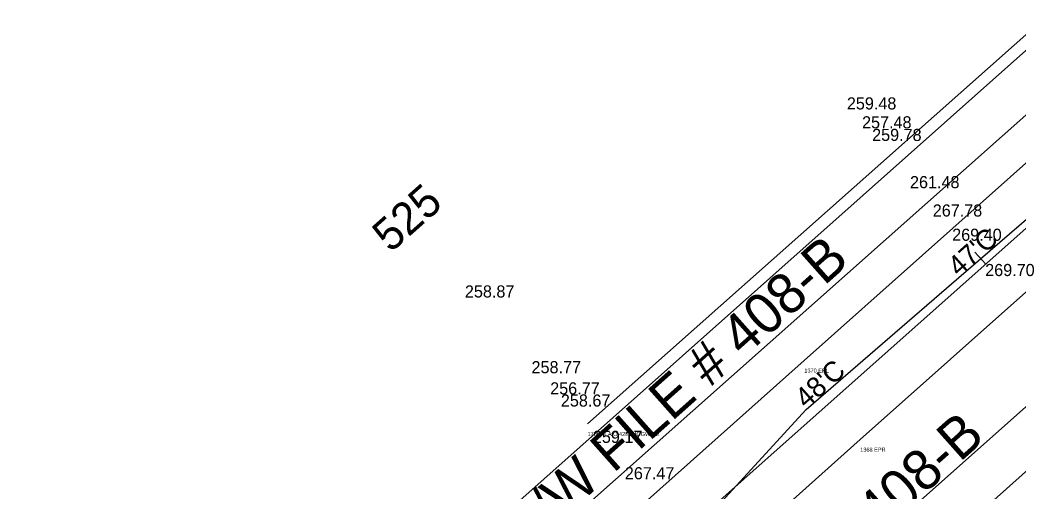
# Model space of a CAD drawing. Extents: x 49683 to 58852, y 49525 to 54803.
# Drawn here: x 53875.1 to 54122.5, y 52022.4 to 52139.1 of the extents above; entities that cross this region are included whole.
import ezdxf

# ---------------------------------------------------------------- set-up
doc = ezdxf.new("R2010")
doc.units = 0
for name, color, linetype in [('Level 1', 7, 'Continuous'), ('Level 11', 7, 'Continuous'), ('Level 13', 7, 'Continuous'), ('Level 18', 7, 'Continuous'), ('Level 19', 7, 'Continuous'), ('Level 20', 7, 'Continuous'), ('Level 21', 7, 'Continuous'), ('Level 25', 7, 'Continuous'), ('Level 3', 7, 'Continuous'), ('Level 32', 7, 'Continuous'), ('Level 48', 7, 'Continuous'), ('Level 53', 7, 'Continuous'), ('Level 58', 7, 'Continuous'), ('Level 8', 7, 'Continuous')]:
    doc.layers.add(name, color=color, linetype=linetype)

msp = doc.modelspace()

# ---------------------------------------------------------------- linework, layer by layer
at = {"layer": 'Level 1'}
for p, q in [((52544.81, 50683.3), (55534.58, 53340.86)), ((54114.5, 52078.58), (54111.84, 52081.57))]:
    msp.add_line(p, q, dxfattribs=at)
at = {"layer": 'Level 11'}
msp.add_line((53894.91, 51911.93), (54324.2, 52292.62), dxfattribs=at)
at = {"layer": 'Level 13'}
for p, q in [((55279.53, 53070), (53969.03, 51905.11)), ((54949.37, 52864.83), (53925.18, 51954.44))]:
    msp.add_line(p, q, dxfattribs=at)
at = {"layer": 'Level 18'}
for p, q in [((54107.86, 52075.28), (54145.7, 52107.97)), ((54070, 52042.61), (54107.86, 52075.28)), ((54036.02, 52005.58), (54070, 52042.61))]:
    msp.add_line(p, q, dxfattribs=at)
at = {"layer": 'Level 19'}
msp.add_line((52714.15, 50773.62), (54181.77, 52078.16), dxfattribs=at)
at = {"layer": 'Level 20'}
msp.add_line((53930.77, 51871.11), (54173.8, 52087.13), dxfattribs=at)
at = {"layer": 'Level 3'}
for p, q in [((54069.54, 52054.72), (54330.23, 52286.79)), ((54083.39, 52035.12), (54346.38, 52269.23)), ((53883.27, 51889.18), (54069.54, 52054.72)), ((53898.74, 51870.57), (54083.39, 52035.12))]:
    msp.add_line(p, q, dxfattribs=at)
at = {"layer": 'Level 8'}
msp.add_line((54015.78, 52039), (54838.64, 52769.14), dxfattribs=at)

# ---------------------------------------------------------------- texts
at = {"layer": 'Level 21'}
msp.add_text('525', height=8, rotation=41.6333, dxfattribs=at).set_placement((53966.97, 52081.24))
at = {"layer": 'Level 25'}
for p in [(53984.2, 51992.86), (54017.83, 51949.17)]:
    msp.add_text("33' R/W FILE # 408-B", height=10, rotation=41.6333, dxfattribs=at).set_placement(p)
at = {"layer": 'Level 32'}
for s, p in [('259.48', (54080.09, 52116.9)), ('257.48', (54083.85, 52112.22)), ('259.78', (54086.35, 52109.1)), ('261.48', (54095.74, 52097.4)), ('267.78', (54101.38, 52090.38)), ('269.40', (54106.2, 52084.37)), ('269.70', (54114.38, 52075.63)), ('258.87', (53985.4, 52070.32)), ('258.77', (54001.92, 52051.56)), ('256.77', (54006.54, 52046.31)), ('258.67', (54009.19, 52043.3)), ('259.17', (54017.12, 52034.3)), ('267.47', (54025.05, 52025.29))]:
    msp.add_text(s, height=3, dxfattribs=at).set_placement(p)
at = {"layer": 'Level 48'}
for s, p in [("47'C", (54107.86, 52075.28)), ("48'C", (54070, 52042.61))]:
    msp.add_text(s, height=5, rotation=41.6334, dxfattribs=at).set_placement(p)
at = {"layer": 'Level 53'}
for s, p in [('1370 EPL', (54069.54, 52051.72)), ('1368 EPR', (54083.39, 52032.12))]:
    msp.add_text(s, height=1, dxfattribs=at).set_placement(p)
at = {"layer": 'Level 58'}
msp.add_text('1705 FLA O 42IN HOGWIRE', height=1, dxfattribs=at).set_placement((54015.78, 52036))

doc.saveas('drawing.dxf')
